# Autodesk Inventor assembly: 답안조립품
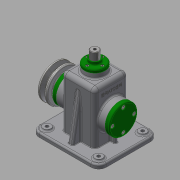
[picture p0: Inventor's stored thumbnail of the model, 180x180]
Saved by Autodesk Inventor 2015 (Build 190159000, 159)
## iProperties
Created: 2016-06
Part Number: 답안조립품
Document SubType Name: Assembly
Designer: aa
Author: aa
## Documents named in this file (19)
- C:\Users\aa\Manufacturing2급-곽행석\답안조립품.iam
- C:\Users\aa\Manufacturing2급-곽행석\1-본체.ipt
- C:\Users\aa\Manufacturing2급-곽행석\베어링 15 x 35 x 11.ipt
- C:\Users\aa\Manufacturing2급-곽행석\편심축.ipt
- C:\Users\aa\Manufacturing2급-곽행석\링크.ipt
- C:\Users\aa\Manufacturing2급-곽행석\슬라이드바.ipt
- C:\Users\aa\Manufacturing2급-곽행석\고정핀.ipt
- C:\Users\aa\Manufacturing2급-곽행석\멈춤링 6 x 5.ipt
- C:\Users\aa\Manufacturing2급-곽행석\뒤커버.ipt
- C:\Users\aa\Manufacturing2급-곽행석\앞커버.ipt
- C:\Users\aa\Manufacturing2급-곽행석\와셔.ipt
- C:\Users\aa\Manufacturing2급-곽행석\멈춤링 15 x 1.ipt
- C:\Users\aa\Manufacturing2급-곽행석\오일실 15 25 7.ipt
- C:\Users\aa\Manufacturing2급-곽행석\V-벨트풀리.ipt
- C:\Users\aa\Manufacturing2급-곽행석\키 5 x 5 x 14.ipt
- C:\Users\aa\Manufacturing2급-곽행석\상부부시.ipt
- C:\Users\aa\Manufacturing2급-곽행석\볼트 M6 x 12.ipt
- C:\Users\aa\Manufacturing2급-곽행석\볼트 M3 x 8.ipt
- C:\Users\aa\Manufacturing2급-곽행석\볼트 M4 x 10.ipt
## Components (24 placed, 6 different names)
1. 1-본체:1 — 각도:1
2. 고정핀:1 — 플러쉬:2, 각도:2, 플러쉬:4, 각도:3
3. V-벨트풀리:1 — 각도:1
4. ISO 4018 M6 x 12:1
5. ISO 4762 M3 x 8:1
6. ISO 4762 M3 x 8:2
7. ISO 4762 M3 x 8:3
8. ISO 4762 M3 x 8:4
9. ISO 4762 M4 x 10:1
10. ISO 4762 M4 x 10:2
11. ISO 4762 M4 x 10:3
12. ISO 4762 M4 x 10:4
13. ISO 4762 M4 x 10:5
14. ISO 4762 M4 x 10:6
15. ISO 4762 M4 x 10:7
16. ISO 4762 M4 x 10:8
17. ISO 4762 M4 x 10:9
18. ISO 4762 M4 x 10:10
19. ISO 4762 M4 x 10:11
20. ISO 4762 M4 x 10:12
21. ISO 4762 M4 x 10:13
22. ISO 4762 M4 x 10:14
23. ISO 4762 M4 x 10:15
24. ISO 4762 M4 x 10:16
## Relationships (5: Angle 3, Flush 2)
- 플러쉬:2 [Flush]: 고정핀:1
- 각도:1 [Angle]: 1-본체:1 ↔ V-벨트풀리:1
- 각도:2 [Angle]: 고정핀:1
- 플러쉬:4 [Flush]: 고정핀:1
- 각도:3 [Angle]: 고정핀:1
